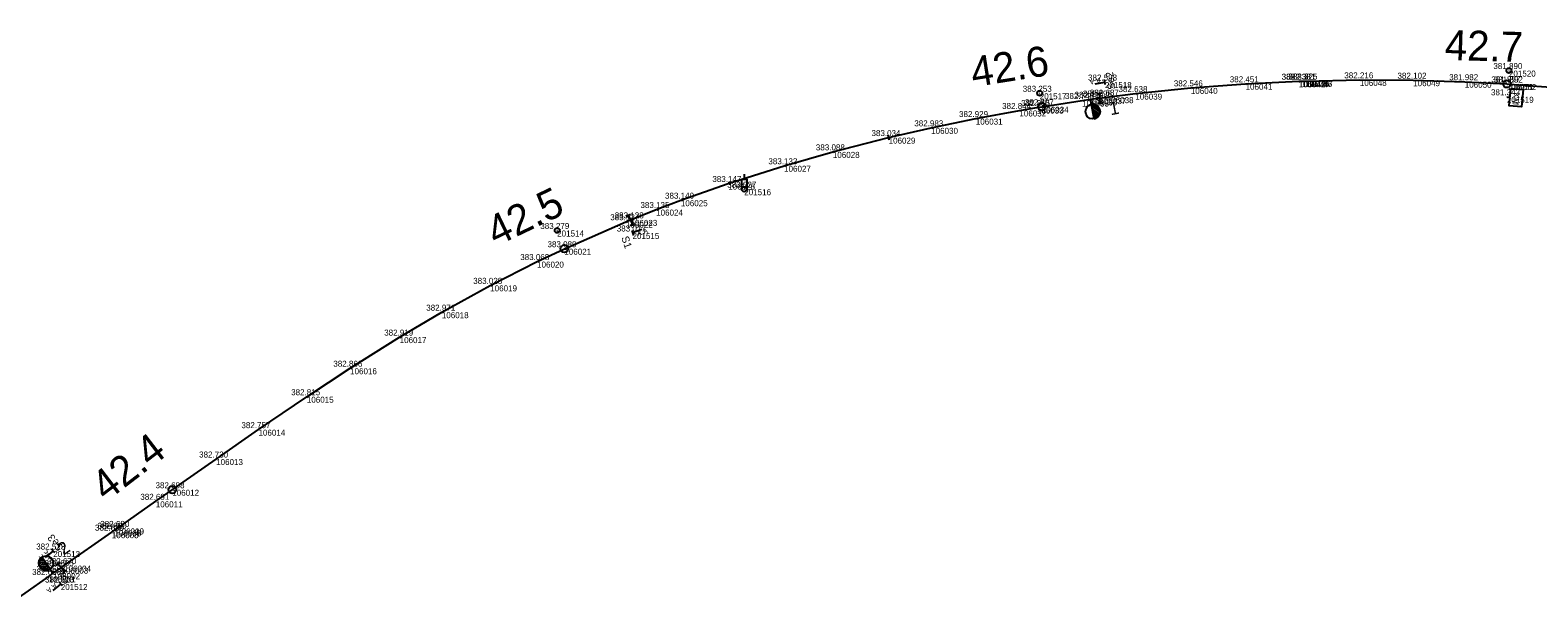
# Model space of a CAD drawing. Extents: x -545715 to -485912, y -1154994 to -1140055.
# Drawn here: x -513420.3 to -513119, y -1143690.9 to -1143575.1 of the extents above; entities that cross this region are included whole.
import ezdxf

# ---------------------------------------------------------------- set-up
doc = ezdxf.new("R2010")
doc.units = 0
for name, color, linetype in [('Vrstva 1', 7, 'Continuous'), ('Vrstva 2', 7, 'Continuous'), ('Vrstva 3', 7, 'Continuous'), ('Vrstva 4', 7, 'Continuous'), ('Vrstva 50', 7, 'Continuous'), ('Vrstva 6', 7, 'Continuous'), ('Vrstva 60', 7, 'Continuous'), ('Vrstva 61', 7, 'Continuous'), ('Vrstva 7', 7, 'Continuous')]:
    doc.layers.add(name, color=color, linetype=linetype)

msp = doc.modelspace()

# ---------------------------------------------------------------- linework, layer by layer
at = {"layer": 'Vrstva 1'}
for p, q in [((-513188.32, -1143586.66), (-513177.37, -1143585.83)), ((-513177.37, -1143585.83), (-513166.73, -1143585.32)), ((-513166.73, -1143585.32), (-513166.04, -1143585.3)), ((-513166.04, -1143585.3), (-513165.4, -1143585.28)), ((-513165.4, -1143585.28), (-513154.53, -1143585.05)), ((-513154.53, -1143585.05), (-513143.87, -1143585.11)), ((-513143.87, -1143585.11), (-513133.56, -1143585.41)), ((-513133.56, -1143585.41), (-513125.13, -1143585.85)), ((-513125.13, -1143585.85), (-513124.64, -1143585.89)), ((-513124.64, -1143585.89), (-513115.51, -1143586.57)), ((-513218.1, -1143590.41), (-513210.04, -1143589.17)), ((-513210.04, -1143589.17), (-513208.38, -1143588.93)), ((-513208.38, -1143588.93), (-513206.58, -1143588.69)), ((-513206.58, -1143588.69), (-513205.12, -1143588.5)), ((-513205.12, -1143588.5), (-513199.41, -1143587.79)), ((-513199.41, -1143587.79), (-513188.32, -1143586.66)), ((-513231.3, -1143592.78), (-513222.58, -1143591.16)), ((-513222.58, -1143591.16), (-513219.1, -1143590.58)), ((-513219.1, -1143590.58), (-513218.1, -1143590.41)), ((-513248.72, -1143596.58), (-513240.22, -1143594.63)), ((-513240.22, -1143594.63), (-513231.3, -1143592.78)), ((-513259.87, -1143599.43), (-513248.72, -1143596.58)), ((-513269.62, -1143602.21), (-513259.87, -1143599.43)), ((-513280.78, -1143605.76), (-513269.62, -1143602.21)), ((-513290.25, -1143609.09), (-513280.78, -1143605.76)), ((-513295.19, -1143610.96), (-513290.25, -1143609.09)), ((-513313.54, -1143618.78), (-513301.22, -1143613.38)), ((-513301.22, -1143613.38), (-513300.33, -1143613.02)), ((-513300.33, -1143613.02), (-513295.19, -1143610.96)), ((-513318.99, -1143621.35), (-513313.54, -1143618.78)), ((-513328.36, -1143626.1), (-513318.99, -1143621.35)), ((-513338.03, -1143631.46), (-513328.36, -1143626.1)), ((-513346.46, -1143636.44), (-513338.03, -1143631.46)), ((-513356.37, -1143642.66), (-513346.46, -1143636.44)), ((-513365.01, -1143648.35), (-513356.37, -1143642.66)), ((-513374.68, -1143654.93), (-513365.01, -1143648.35)), ((-513383.14, -1143660.8), (-513374.68, -1143654.93)), ((-513391.91, -1143666.94), (-513383.14, -1143660.8)), ((-513395.21, -1143669.25), (-513391.91, -1143666.94)), ((-513402.93, -1143674.67), (-513395.21, -1143669.25)), ((-513413.51, -1143682.09), (-513404, -1143675.41)), ((-513404, -1143675.41), (-513403.47, -1143675.04)), ((-513403.47, -1143675.04), (-513402.93, -1143674.67)), ((-513415.7, -1143683.62), (-513414.08, -1143682.49)), ((-513414.08, -1143682.49), (-513413.51, -1143682.09)), ((-513426.06, -1143690.93), (-513416.59, -1143684.25)), ((-513416.59, -1143684.25), (-513415.7, -1143683.62))]:
    msp.add_line(p, q, dxfattribs=at)
at = {"layer": 'Vrstva 2'}
for p, q in [((-513208.19, -1143589.94), (-513208.38, -1143588.93)), ((-513208.19, -1143589.94), (-513207.65, -1143592.82)), ((-513208.19, -1143589.94), (-513208.19, -1143589.94)), ((-513207.65, -1143592.82), (-513208.19, -1143589.94)), ((-513208.11, -1143590.36), (-513206.46, -1143591.49)), ((-513208.08, -1143589.93), (-513206.51, -1143591)), ((-513208.01, -1143590.88), (-513206.55, -1143591.88)), ((-513207.91, -1143591.4), (-513206.72, -1143592.22)), ((-513207.82, -1143591.92), (-513206.98, -1143592.5)), ((-513207.72, -1143592.45), (-513207.33, -1143592.72)), ((-513248.61, -1143597.07), (-513248.84, -1143596.1)), ((-513416.85, -1143682.01), (-513418.6, -1143681.72)), ((-513417.16, -1143681.58), (-513418.59, -1143681.34)), ((-513416.54, -1143682.44), (-513418.51, -1143682.11)), ((-513417.47, -1143681.15), (-513418.47, -1143680.98)), ((-513416.39, -1143682.84), (-513418.27, -1143682.54)), ((-513417.78, -1143680.72), (-513418.25, -1143680.64)), ((-513416.3, -1143682.79), (-513418, -1143680.41)), ((-513418, -1143680.41), (-513416.3, -1143682.79)), ((-513416.3, -1143682.79), (-513415.7, -1143683.62)), ((-513416.3, -1143682.79), (-513416.3, -1143682.79))]:
    msp.add_line(p, q, dxfattribs=at)
for centre in [(-513207.92, -1143591.39), (-513417.15, -1143681.59)]:
    msp.add_circle(centre, 1.46, dxfattribs=at)
for centre, start, end in [((-513207.92, -1143591.38), 280.6292, 100.5901), ((-513417.15, -1143681.6), 125.6292, 305.5901)]:
    msp.add_arc(centre, 1.46, start, end, dxfattribs=at)
at = {"layer": 'Vrstva 3'}
for p, q in [((-513207.16, -1143587.74), (-513206.17, -1143587.65)), ((-513206.66, -1143587.69), (-513206.49, -1143589.69)), ((-513206.99, -1143589.73), (-513205.99, -1143589.64)), ((-513301.21, -1143612.33), (-513300.3, -1143611.9)), ((-513300.76, -1143612.11), (-513299.91, -1143613.93)), ((-513300.36, -1143614.14), (-513299.46, -1143613.71)), ((-513415.11, -1143682.04), (-513414.34, -1143681.4)), ((-513414.72, -1143681.72), (-513413.44, -1143683.25)), ((-513413.82, -1143683.57), (-513413.05, -1143682.93))]:
    msp.add_line(p, q, dxfattribs=at)
at = {"layer": 'Vrstva 4'}
msp.add_line((-513295.19, -1143610.96), (-513290.25, -1143609.09), dxfattribs=at)
at = {"layer": 'Vrstva 50'}
for p, q in [((-513277.58, -1143603.89), (-513277.58, -1143604.89)), ((-513277.53, -1143606.89), (-513277.63, -1143606.89))]:
    msp.add_line(p, q, dxfattribs=at)
msp.add_lwpolyline([(-513278.09, -1143606.89), (-513278.08, -1143604.89), (-513277.07, -1143604.89), (-513277.07, -1143606.89)], dxfattribs=at)
msp.add_circle((-513277.58, -1143606.89), 0.506, dxfattribs=at)
at = {"layer": 'Vrstva 6'}
for p, q in [((-513207.44, -1143585.84), (-513205.49, -1143585.49)), ((-513205.41, -1143585.98), (-513205.58, -1143585)), ((-513300.08, -1143615.17), (-513299.74, -1143616.11)), ((-513298.05, -1143614.96), (-513299.91, -1143615.64)), ((-513417.22, -1143680.45), (-513415.7, -1143679.18)), ((-513415.38, -1143679.56), (-513416.03, -1143678.8)), ((-513415.72, -1143687.04), (-513414.2, -1143685.77)), ((-513413.88, -1143686.15), (-513414.52, -1143685.38))]:
    msp.add_line(p, q, dxfattribs=at)
at = {"layer": 'Vrstva 60'}
for p, q in [((-513124.73, -1143583.19), (-513124.73, -1143583.19)), ((-513205.49, -1143585.49), (-513205.49, -1143585.49)), ((-513177.37, -1143585.83), (-513177.37, -1143585.83)), ((-513166.77, -1143585.32), (-513166.77, -1143585.32)), ((-513166.73, -1143585.32), (-513166.73, -1143585.32)), ((-513166.06, -1143585.3), (-513166.06, -1143585.3)), ((-513166.04, -1143585.3), (-513166.04, -1143585.3)), ((-513165.4, -1143585.28), (-513165.4, -1143585.28)), ((-513165.39, -1143585.28), (-513165.39, -1143585.28)), ((-513154.53, -1143585.05), (-513154.53, -1143585.05)), ((-513143.87, -1143585.11), (-513143.87, -1143585.11)), ((-513133.56, -1143585.41), (-513133.56, -1143585.41)), ((-513125.13, -1143585.85), (-513125.13, -1143585.85)), ((-513124.64, -1143585.89), (-513124.64, -1143585.89)), ((-513218.52, -1143587.73), (-513218.52, -1143587.73)), ((-513210.04, -1143589.17), (-513210.04, -1143589.17)), ((-513208.38, -1143588.93), (-513208.38, -1143588.93)), ((-513206.58, -1143588.69), (-513206.58, -1143588.69)), ((-513205.12, -1143588.5), (-513205.12, -1143588.5)), ((-513199.41, -1143587.79), (-513199.41, -1143587.79)), ((-513188.32, -1143586.66), (-513188.32, -1143586.66)), ((-513125.14, -1143588.43), (-513125.14, -1143588.43)), ((-513222.58, -1143591.16), (-513222.58, -1143591.16)), ((-513219.1, -1143590.58), (-513219.1, -1143590.58)), ((-513218.1, -1143590.41), (-513218.1, -1143590.41)), ((-513240.22, -1143594.63), (-513240.22, -1143594.63)), ((-513231.3, -1143592.78), (-513231.3, -1143592.78)), ((-513248.72, -1143596.58), (-513248.72, -1143596.58)), ((-513259.87, -1143599.43), (-513259.87, -1143599.43)), ((-513269.62, -1143602.21), (-513269.62, -1143602.21)), ((-513280.78, -1143605.76), (-513280.78, -1143605.76)), ((-513277.58, -1143606.89), (-513277.58, -1143606.89)), ((-513290.25, -1143609.09), (-513290.25, -1143609.09)), ((-513301.22, -1143613.38), (-513301.22, -1143613.38)), ((-513300.33, -1143613.02), (-513300.33, -1143613.02)), ((-513295.19, -1143610.96), (-513295.19, -1143610.96)), ((-513314.97, -1143615.14), (-513314.97, -1143615.14)), ((-513299.91, -1143615.64), (-513299.91, -1143615.64)), ((-513313.54, -1143618.78), (-513313.54, -1143618.78)), ((-513318.99, -1143621.35), (-513318.99, -1143621.35)), ((-513328.36, -1143626.1), (-513328.36, -1143626.1)), ((-513338.03, -1143631.46), (-513338.03, -1143631.46)), ((-513346.46, -1143636.44), (-513346.46, -1143636.44)), ((-513356.37, -1143642.66), (-513356.37, -1143642.66)), ((-513365.01, -1143648.35), (-513365.01, -1143648.35)), ((-513374.68, -1143654.93), (-513374.68, -1143654.93)), ((-513383.14, -1143660.8), (-513383.14, -1143660.8)), ((-513391.91, -1143666.94), (-513391.91, -1143666.94)), ((-513395.21, -1143669.25), (-513395.21, -1143669.25)), ((-513404, -1143675.41), (-513404, -1143675.41)), ((-513403.99, -1143675.41), (-513403.99, -1143675.41)), ((-513403.47, -1143675.04), (-513403.47, -1143675.04)), ((-513403.47, -1143675.04), (-513403.47, -1143675.04)), ((-513402.93, -1143674.66), (-513402.93, -1143674.66)), ((-513402.93, -1143674.67), (-513402.93, -1143674.67)), ((-513415.7, -1143679.18), (-513415.7, -1143679.18)), ((-513414.08, -1143682.49), (-513414.08, -1143682.49)), ((-513413.51, -1143682.09), (-513413.51, -1143682.09)), ((-513416.59, -1143684.25), (-513416.59, -1143684.25)), ((-513415.7, -1143683.62), (-513415.7, -1143683.62)), ((-513414.2, -1143685.77), (-513414.2, -1143685.77))]:
    msp.add_line(p, q, dxfattribs=at)
at = {"layer": 'Vrstva 7'}
for p, q in [((-513124.78, -1143583.19), (-513124.68, -1143583.19)), ((-513218.57, -1143587.73), (-513218.47, -1143587.73)), ((-513125.14, -1143588.43), (-513124.52, -1143588.49)), ((-513315.02, -1143615.14), (-513314.92, -1143615.14))]:
    msp.add_line(p, q, dxfattribs=at)
msp.add_lwpolyline([(-513124.37, -1143586.75), (-513121.9, -1143586.97), (-513122.2, -1143590.44), (-513124.68, -1143590.22)], close=True, dxfattribs=at)
for centre, radius in [((-513124.73, -1143583.19), 0.5), ((-513125.13, -1143585.85), 0.75), ((-513218.52, -1143587.73), 0.5), ((-513218.1, -1143590.41), 0.75), ((-513314.97, -1143615.14), 0.5), ((-513313.54, -1143618.78), 0.75), ((-513391.91, -1143666.94), 0.75)]:
    msp.add_circle(centre, radius, dxfattribs=at)

# ---------------------------------------------------------------- texts
at = {"layer": 'Vrstva 2'}
for s, rotation, p in [('1', 10.5807, (-513204.33, -1143592.12)), ('2', 35.5807, (-513413.65, -1143680.12))]:
    msp.add_text(s, height=2.5, rotation=rotation, dxfattribs=at).set_placement(p)
at = {"layer": 'Vrstva 6'}
for s, height, rotation, p in [('  A A ', 1, 190, (-513205.67, -1143584.51)), ('Se2', 1.5, 98.4684, (-513203.37, -1143586.87)), ('S1', 1.5, 288.4684, (-513302.18, -1143616.55)), ('  A A ', 1, 20, (-513299.57, -1143616.58)), ('Se3', 1.5, 128.4684, (-513413.59, -1143678.46)), ('  A A ', 1, 220, (-513416.35, -1143678.41)), ('Se4', 1.5, 128.4684, (-513412.09, -1143685.05)), ('  A A ', 1, 220, (-513414.85, -1143685))]:
    msp.add_text(s, height=height, rotation=rotation, dxfattribs=at).set_placement(p)
at = {"layer": 'Vrstva 60'}
for s, p in [('201520', (-513124.73, -1143584.39)), ('201518', (-513205.49, -1143586.69)), ('106041', (-513177.37, -1143587.03)), ('106042', (-513166.77, -1143586.52)), ('106043', (-513166.73, -1143586.52)), ('106044', (-513166.06, -1143586.5)), ('106045', (-513166.04, -1143586.5)), ('106046', (-513165.4, -1143586.48)), ('106047', (-513165.39, -1143586.48)), ('106048', (-513154.53, -1143586.25)), ('106049', (-513143.87, -1143586.31)), ('106050', (-513133.56, -1143586.61)), ('106051', (-513125.13, -1143587.05)), ('106052', (-513124.64, -1143587.08)), ('201517', (-513218.52, -1143588.93)), ('106035', (-513210.04, -1143590.37)), ('106036', (-513208.38, -1143590.13)), ('106037', (-513206.58, -1143589.89)), ('106038', (-513205.12, -1143589.7)), ('106039', (-513199.41, -1143588.99)), ('106040', (-513188.32, -1143587.85)), ('201519', (-513125.14, -1143589.63)), ('106032', (-513222.58, -1143592.36)), ('106033', (-513219.1, -1143591.78)), ('106034', (-513218.1, -1143591.61)), ('106030', (-513240.22, -1143595.83)), ('106031', (-513231.3, -1143593.98)), ('106029', (-513248.72, -1143597.78)), ('106028', (-513259.87, -1143600.63)), ('106027', (-513269.62, -1143603.41)), ('106026', (-513280.78, -1143606.96)), ('201516', (-513277.58, -1143608.09)), ('106025', (-513290.25, -1143610.29)), ('106022', (-513301.22, -1143614.58)), ('106023', (-513300.33, -1143614.22)), ('106024', (-513295.19, -1143612.16)), ('201514', (-513314.97, -1143616.34)), ('201515', (-513299.91, -1143616.84)), ('106021', (-513313.54, -1143619.98)), ('106020', (-513318.99, -1143622.55)), ('106019', (-513328.36, -1143627.3)), ('106018', (-513338.03, -1143632.66)), ('106017', (-513346.46, -1143637.64)), ('106016', (-513356.37, -1143643.86)), ('106015', (-513365.01, -1143649.55)), ('106014', (-513374.68, -1143656.13)), ('106013', (-513383.14, -1143662)), ('106012', (-513391.91, -1143668.14)), ('106011', (-513395.21, -1143670.45)), ('106006', (-513403.99, -1143676.61)), ('106005', (-513404, -1143676.61)), ('106008', (-513403.47, -1143676.24)), ('106007', (-513403.47, -1143676.24)), ('106010', (-513402.93, -1143675.86)), ('106009', (-513402.93, -1143675.87)), ('201513', (-513415.7, -1143680.38)), ('106003', (-513414.08, -1143683.69)), ('106004', (-513413.51, -1143683.29)), ('106001', (-513416.59, -1143685.45)), ('106002', (-513415.7, -1143684.82)), ('201512', (-513414.2, -1143686.97))]:
    msp.add_text(s, height=1.2, dxfattribs=at).set_placement(p)
at = {"layer": 'Vrstva 61'}
for s, p in [('381.890', (-513127.84, -1143582.89)), ('383.253', (-513221.92, -1143587.43)), ('382.598', (-513208.87, -1143585.19)), ('382.638', (-513202.78, -1143587.49)), ('382.546', (-513191.72, -1143586.35)), ('382.451', (-513180.54, -1143585.53)), ('382.338', (-513170.18, -1143585.02)), ('382.338', (-513170.14, -1143585.02)), ('382.331', (-513169.2, -1143585)), ('382.331', (-513169.19, -1143585)), ('382.325', (-513168.81, -1143584.98)), ('382.325', (-513168.8, -1143584.98)), ('382.216', (-513157.64, -1143584.75)), ('382.102', (-513147.01, -1143584.81)), ('381.982', (-513136.68, -1143585.11)), ('381.897', (-513128.25, -1143585.55)), ('381.892', (-513127.75, -1143585.58)), ('382.815', (-513222.24, -1143590.28)), ('382.807', (-513221.5, -1143590.11)), ('382.740', (-513213.47, -1143588.87)), ('382.714', (-513211.55, -1143588.63)), ('382.696', (-513209.89, -1143588.39)), ('382.687', (-513208.5, -1143588.2)), ('381.343', (-513128.32, -1143588.13)), ('382.929', (-513234.65, -1143592.48)), ('382.844', (-513226.04, -1143590.86)), ('383.034', (-513252.15, -1143596.28)), ('382.983', (-513243.59, -1143594.33)), ('383.088', (-513263.27, -1143599.13)), ('383.133', (-513272.76, -1143601.91)), ('383.147', (-513283.95, -1143605.46)), ('383.027', (-513280.98, -1143606.59)), ('383.135', (-513298.33, -1143610.66)), ('383.140', (-513293.42, -1143608.79)), ('383.127', (-513304.37, -1143613.08)), ('383.128', (-513303.48, -1143612.72)), ('383.279', (-513318.35, -1143614.84)), ('383.017', (-513303.06, -1143615.34)), ('383.089', (-513316.91, -1143618.48)), ('383.068', (-513322.36, -1143621.05)), ('383.028', (-513331.76, -1143625.8)), ('382.971', (-513341.15, -1143631.16)), ('382.919', (-513349.55, -1143636.14)), ('382.866', (-513359.72, -1143642.36)), ('382.815', (-513368.15, -1143648.05)), ('382.757', (-513378.09, -1143654.63)), ('382.730', (-513386.55, -1143660.5)), ('382.691', (-513398.3, -1143668.95)), ('382.698', (-513395.26, -1143666.64)), ('382.680', (-513406.84, -1143674.74)), ('382.680', (-513406.84, -1143674.74)), ('382.680', (-513406.3, -1143674.36)), ('382.680', (-513406.3, -1143674.37)), ('382.680', (-513407.37, -1143675.11)), ('382.679', (-513407.35, -1143675.11)), ('382.523', (-513419.11, -1143678.88)), ('382.660', (-513419.93, -1143683.95)), ('382.663', (-513419.05, -1143683.32)), ('382.665', (-513417.43, -1143682.19)), ('382.670', (-513416.89, -1143681.79)), ('382.513', (-513417.35, -1143685.47))]:
    msp.add_text(s, height=1.2, dxfattribs=at).set_placement(p)
at = {"layer": 'Vrstva 7'}
for s, height, rotation, p in [('42.7', 6, 358.2855, (-513137.62, -1143581.03)), ('42.6', 6, 9.0049, (-513231.8, -1143586.51)), ('KM', 1.247, 265, (-513123.82, -1143587.53)), ('42.5', 6, 25.5884, (-513327.23, -1143618.4)), ('42.4', 6, 37.535, (-513405.14, -1143669.45))]:
    msp.add_text(s, height=height, rotation=rotation, dxfattribs=at).set_placement(p)

doc.saveas('drawing.dxf')
